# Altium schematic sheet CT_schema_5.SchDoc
size 143 x 108 mm
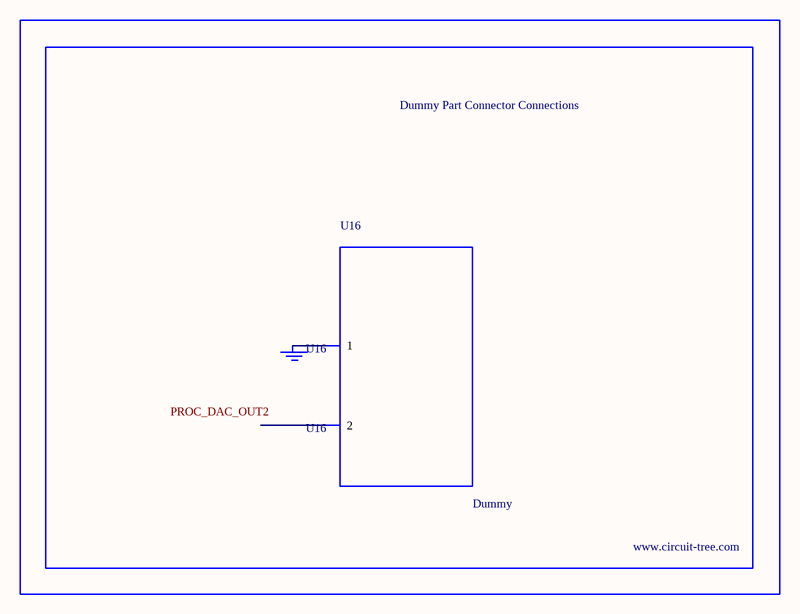
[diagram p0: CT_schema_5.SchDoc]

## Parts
BORDER4  (no value)
GND_INSTANCE_4_0  (no value)
U16  Dummy  [DUMMY_PACKAGE_136]

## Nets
NetGND_INSTANCE_4_0_0: GND_INSTANCE_4_0.0(GND) U16.1

Not connected (* = marked no-connect by the designer): U16 2

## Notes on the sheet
- Labels drawn without touching a wire or pin: PROC_DAC_OUT2

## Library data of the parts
BORDER4 = BORDER_PAGE4
GND_INSTANCE_4_0 = GND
